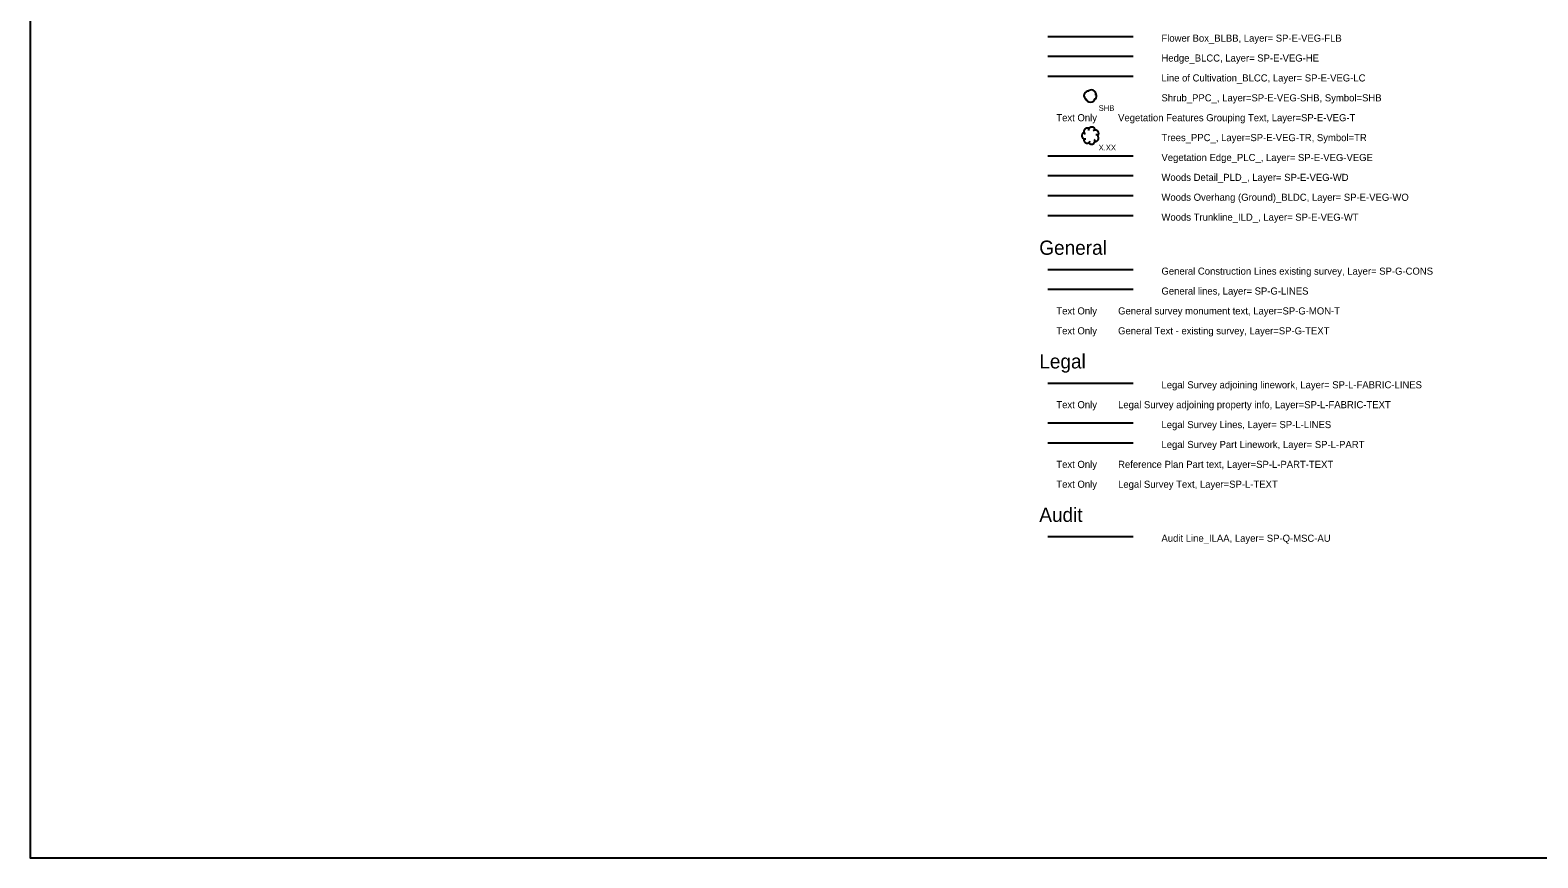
# Model space of a CAD drawing. Extents: x 500528 to 502626, y 4210261 to 4212624.
# Drawn here: x 500528 to 501059, y 4210261 to 4210552 of the extents above; entities that cross this region are included whole.
import ezdxf

# ---------------------------------------------------------------- set-up
doc = ezdxf.new("R2010")
doc.units = 0
for name, color, linetype in [('Default', 7, 'Continuous'), ('SP-E-VEG-FLB', 7, 'Continuous'), ('SP-E-VEG-HE', 7, 'Continuous'), ('SP-E-VEG-LC', 7, 'Continuous'), ('SP-E-VEG-SHB', 7, 'Continuous'), ('SP-E-VEG-T', 7, 'Continuous'), ('SP-E-VEG-TR', 7, 'Continuous'), ('SP-E-VEG-VEGE', 7, 'Continuous'), ('SP-E-VEG-WD', 7, 'Continuous'), ('SP-E-VEG-WO', 7, 'Continuous'), ('SP-E-VEG-WT', 7, 'Continuous'), ('SP-G-CONS', 7, 'Continuous'), ('SP-G-LINES', 7, 'Continuous'), ('SP-G-MON-T', 7, 'Continuous'), ('SP-G-TEXT', 7, 'Continuous'), ('SP-L-FABRIC-LINES', 7, 'Continuous'), ('SP-L-FABRIC-TEXT', 7, 'Continuous'), ('SP-L-LINES', 7, 'Continuous'), ('SP-L-PART', 7, 'Continuous'), ('SP-L-PART-TEXT', 7, 'Continuous'), ('SP-L-TEXT', 7, 'Continuous'), ('SP-Q-MSC-AU', 7, 'Continuous')]:
    doc.layers.add(name, color=color, linetype=linetype)

# ---------------------------------------------------------------- blocks, each defined once
blk = doc.blocks.new('SHB')
at = {"layer": 'SP-E-VEG-SHB'}
for centre, radius, start, end in [((-0.069, 0.02), 0.161, 80.6965, 246.9293), ((0.031, 0.052), 0.166, 353.6146, 139.6631), ((0.045, 0.007), 0.172, 296.4869, 48.0431), ((0, -0.044), 0.172, 193.3596, 346.7738)]:
    blk.add_arc(centre, radius, start, end, dxfattribs=at)
at = {"layer": 'SP-E-VEG-T'}
blk.add_text('SHB', height=0.2, dxfattribs=at).set_placement((0.29, -0.52))
blk = doc.blocks.new('TR')
at = {"layer": 'SP-E-VEG-TR'}
for points in [[(-0.226, 0.123), (-0.246, 0.113), (-0.264, 0.099), (-0.279, 0.083), (-0.29, 0.064), (-0.298, 0.043), (-0.302, 0.021), (-0.302, -0.001), (-0.297, -0.023), (-0.289, -0.044), (-0.277, -0.063), (-0.261, -0.079), (-0.243, -0.092), (-0.223, -0.102), (-0.202, -0.107), (-0.179, -0.109), (-0.157, -0.106)], [(-0.05, 0.258), (-0.071, 0.268), (-0.092, 0.273), (-0.115, 0.274), (-0.137, 0.272), (-0.158, 0.265), (-0.177, 0.254), (-0.195, 0.24), (-0.209, 0.223), (-0.22, 0.203), (-0.227, 0.182), (-0.23, 0.16), (-0.229, 0.138), (-0.224, 0.116), (-0.215, 0.096), (-0.202, 0.077), (-0.187, 0.062)], [(0.165, 0.205), (0.16, 0.227), (0.15, 0.247), (0.138, 0.266), (0.122, 0.281), (0.103, 0.293), (0.082, 0.302), (0.061, 0.307), (0.038, 0.307), (0.016, 0.304), (-0.005, 0.296), (-0.024, 0.285), (-0.041, 0.27), (-0.054, 0.252), (-0.065, 0.233), (-0.071, 0.211), (-0.074, 0.189)], [(0.258, 0.004), (0.272, 0.022), (0.282, 0.041), (0.288, 0.063), (0.29, 0.085), (0.288, 0.107), (0.282, 0.129), (0.272, 0.149), (0.259, 0.166), (0.242, 0.181), (0.223, 0.193), (0.202, 0.201), (0.18, 0.205), (0.158, 0.205), (0.136, 0.201), (0.115, 0.192), (0.096, 0.18)], [(0.158, -0.194), (0.181, -0.194), (0.203, -0.19), (0.223, -0.181), (0.242, -0.169), (0.258, -0.153), (0.271, -0.135), (0.28, -0.115), (0.286, -0.093), (0.287, -0.071), (0.285, -0.049), (0.278, -0.028), (0.267, -0.008), (0.253, 0.009), (0.236, 0.024), (0.217, 0.035), (0.196, 0.042)], [(-0.23, -0.099), (-0.234, -0.121), (-0.235, -0.143), (-0.231, -0.165), (-0.224, -0.186), (-0.212, -0.205), (-0.197, -0.222), (-0.18, -0.235), (-0.16, -0.246), (-0.138, -0.252), (-0.116, -0.254), (-0.094, -0.252), (-0.073, -0.246), (-0.052, -0.237), (-0.035, -0.223), (-0.02, -0.207), (-0.008, -0.188)], [(-0.059, -0.24), (-0.045, -0.257), (-0.027, -0.272), (-0.008, -0.282), (0.013, -0.289), (0.035, -0.292), (0.058, -0.291), (0.079, -0.286), (0.1, -0.277), (0.118, -0.264), (0.134, -0.248), (0.146, -0.23), (0.155, -0.209), (0.16, -0.187), (0.16, -0.165), (0.157, -0.143), (0.149, -0.122)]]:
    blk.add_lwpolyline(points, dxfattribs=at)
at = {"layer": 'SP-E-VEG-T'}
blk.add_text('X.XX', height=0.2, dxfattribs=at).set_placement((0.29, -0.512))

msp = doc.modelspace()

# ---------------------------------------------------------------- linework, layer by layer
at = {"layer": 'Default'}
msp.add_lwpolyline([(500528.35, 4212623.85), (500528.35, 4210260.5), (502626.48, 4210260.5), (502626.48, 4212623.85), (500528.35, 4212623.85)], dxfattribs=at)
msp.add_lwpolyline([(500528.35, 4210260.5), (502626.48, 4210260.5), (502626.48, 4212623.85), (500528.35, 4212623.85)], close=True, dxfattribs=at)
at = {"layer": 'SP-E-VEG-FLB'}
msp.add_line((500886.55, 4210549.59), (500916.55, 4210549.59), dxfattribs=at)
at = {"layer": 'SP-E-VEG-HE'}
msp.add_line((500886.55, 4210542.59), (500916.55, 4210542.59), dxfattribs=at)
at = {"layer": 'SP-E-VEG-LC'}
msp.add_line((500886.55, 4210535.59), (500916.55, 4210535.59), dxfattribs=at)
at = {"layer": 'SP-E-VEG-VEGE'}
msp.add_line((500886.55, 4210507.59), (500916.55, 4210507.59), dxfattribs=at)
at = {"layer": 'SP-E-VEG-WD'}
msp.add_line((500886.55, 4210500.59), (500916.55, 4210500.59), dxfattribs=at)
at = {"layer": 'SP-E-VEG-WO'}
msp.add_line((500886.55, 4210493.59), (500916.55, 4210493.59), dxfattribs=at)
at = {"layer": 'SP-E-VEG-WT'}
msp.add_line((500886.55, 4210486.59), (500916.55, 4210486.59), dxfattribs=at)
at = {"layer": 'SP-G-CONS'}
msp.add_line((500886.55, 4210467.59), (500916.55, 4210467.59), dxfattribs=at)
at = {"layer": 'SP-G-LINES'}
msp.add_line((500886.55, 4210460.59), (500916.55, 4210460.59), dxfattribs=at)
at = {"layer": 'SP-L-FABRIC-LINES'}
msp.add_line((500886.55, 4210427.59), (500916.55, 4210427.59), dxfattribs=at)
at = {"layer": 'SP-L-LINES'}
msp.add_line((500886.55, 4210413.59), (500916.55, 4210413.59), dxfattribs=at)
at = {"layer": 'SP-L-PART'}
msp.add_line((500886.55, 4210406.59), (500916.55, 4210406.59), dxfattribs=at)
at = {"layer": 'SP-Q-MSC-AU'}
msp.add_line((500886.55, 4210373.59), (500916.55, 4210373.59), dxfattribs=at)

# ---------------------------------------------------------------- block references
at = {"layer": 'SP-E-VEG-SHB', "xscale": 10, "yscale": 10}
msp.add_blockref('SHB', (500901.55, 4210528.59), dxfattribs=at)
at = {"layer": 'SP-E-VEG-TR', "xscale": 10, "yscale": 10}
msp.add_blockref('TR', (500901.55, 4210514.59), dxfattribs=at)

# ---------------------------------------------------------------- texts
at = {"layer": 'Default'}
for s, p in [('General ', (500883.55, 4210472.74)), ('Legal  ', (500883.55, 4210432.74)), ('Audit ', (500883.55, 4210378.74))]:
    msp.add_text(s, height=5, dxfattribs=at).set_placement(p)
at = {"layer": 'SP-E-VEG-FLB'}
msp.add_text('Flower Box_BLBB, Layer= SP-E-VEG-FLB ', height=2.5, dxfattribs=at).set_placement((500926.55, 4210547.74))
at = {"layer": 'SP-E-VEG-HE'}
msp.add_text('Hedge_BLCC, Layer= SP-E-VEG-HE ', height=2.5, dxfattribs=at).set_placement((500926.55, 4210540.74))
at = {"layer": 'SP-E-VEG-LC'}
msp.add_text('Line of Cultivation_BLCC, Layer= SP-E-VEG-LC ', height=2.5, dxfattribs=at).set_placement((500926.55, 4210533.74))
at = {"layer": 'SP-E-VEG-SHB'}
msp.add_text('Shrub_PPC_, Layer=SP-E-VEG-SHB, Symbol=SHB ', height=2.5, dxfattribs=at).set_placement((500926.55, 4210526.74))
at = {"layer": 'SP-E-VEG-T'}
msp.add_text('Text Only        Vegetation Features Grouping Text, Layer=SP-E-VEG-T', height=2.5, dxfattribs=at).set_placement((500889.55, 4210519.74))
at = {"layer": 'SP-E-VEG-TR'}
msp.add_text('Trees_PPC_, Layer=SP-E-VEG-TR, Symbol=TR ', height=2.5, dxfattribs=at).set_placement((500926.55, 4210512.74))
at = {"layer": 'SP-E-VEG-VEGE'}
msp.add_text('Vegetation Edge_PLC_, Layer= SP-E-VEG-VEGE ', height=2.5, dxfattribs=at).set_placement((500926.55, 4210505.74))
at = {"layer": 'SP-E-VEG-WD'}
msp.add_text('Woods Detail_PLD_, Layer= SP-E-VEG-WD ', height=2.5, dxfattribs=at).set_placement((500926.55, 4210498.74))
at = {"layer": 'SP-E-VEG-WO'}
msp.add_text('Woods Overhang (Ground)_BLDC, Layer= SP-E-VEG-WO ', height=2.5, dxfattribs=at).set_placement((500926.55, 4210491.74))
at = {"layer": 'SP-E-VEG-WT'}
msp.add_text('Woods Trunkline_ILD_, Layer= SP-E-VEG-WT ', height=2.5, dxfattribs=at).set_placement((500926.55, 4210484.74))
at = {"layer": 'SP-G-CONS'}
msp.add_text('General Construction Lines existing survey, Layer= SP-G-CONS ', height=2.5, dxfattribs=at).set_placement((500926.55, 4210465.74))
at = {"layer": 'SP-G-LINES'}
msp.add_text('General lines, Layer= SP-G-LINES ', height=2.5, dxfattribs=at).set_placement((500926.55, 4210458.74))
at = {"layer": 'SP-G-MON-T'}
msp.add_text('Text Only        General survey monument text, Layer=SP-G-MON-T', height=2.5, dxfattribs=at).set_placement((500889.55, 4210451.74))
at = {"layer": 'SP-G-TEXT'}
msp.add_text('Text Only        General Text - existing survey, Layer=SP-G-TEXT', height=2.5, dxfattribs=at).set_placement((500889.55, 4210444.74))
at = {"layer": 'SP-L-FABRIC-LINES'}
msp.add_text('Legal Survey adjoining linework, Layer= SP-L-FABRIC-LINES ', height=2.5, dxfattribs=at).set_placement((500926.55, 4210425.74))
at = {"layer": 'SP-L-FABRIC-TEXT'}
msp.add_text('Text Only        Legal Survey adjoining property info, Layer=SP-L-FABRIC-TEXT', height=2.5, dxfattribs=at).set_placement((500889.55, 4210418.74))
at = {"layer": 'SP-L-LINES'}
msp.add_text('Legal Survey Lines, Layer= SP-L-LINES ', height=2.5, dxfattribs=at).set_placement((500926.55, 4210411.74))
at = {"layer": 'SP-L-PART'}
msp.add_text('Legal Survey Part Linework, Layer= SP-L-PART ', height=2.5, dxfattribs=at).set_placement((500926.55, 4210404.74))
at = {"layer": 'SP-L-PART-TEXT'}
msp.add_text('Text Only        Reference Plan Part text, Layer=SP-L-PART-TEXT', height=2.5, dxfattribs=at).set_placement((500889.55, 4210397.74))
at = {"layer": 'SP-L-TEXT'}
msp.add_text('Text Only        Legal Survey Text, Layer=SP-L-TEXT', height=2.5, dxfattribs=at).set_placement((500889.55, 4210390.74))
at = {"layer": 'SP-Q-MSC-AU'}
msp.add_text('Audit Line_ILAA, Layer= SP-Q-MSC-AU ', height=2.5, dxfattribs=at).set_placement((500926.55, 4210371.74))

doc.saveas('drawing.dxf')
